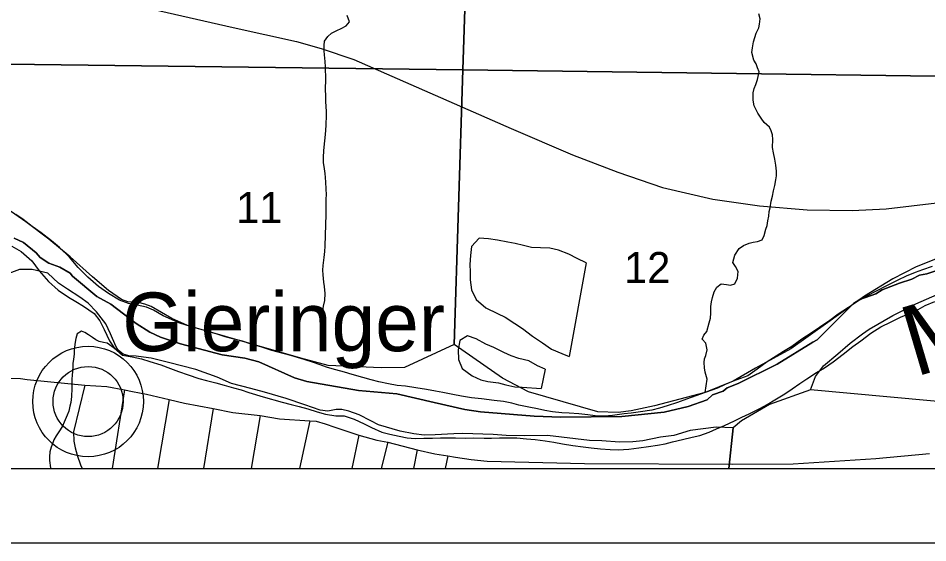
# Model space of a CAD drawing. Extents: x -7.5 to 26.5, y 3.5 to 25.5.
# Drawn here: x -0.973 to 0.251, y 17.5 to 18.207 of the extents above; entities that cross this region are included whole.
import ezdxf

# ---------------------------------------------------------------- set-up
doc = ezdxf.new("R2010")
doc.units = 0
for name, color, linetype in [('GM_X_Corporation', 7, 'Continuous'), ('GM_X_County_Road', 7, 'Continuous'), ('GM_X_Major_River', 7, 'Continuous'), ('GM_X_Major_River_Text', 7, 'Continuous'), ('GM_X_Minor_Lake', 7, 'Continuous'), ('GM_X_Minor_River', 7, 'Continuous'), ('GM_X_Section_Text', 7, 'Continuous'), ('GM_X_State_Route', 7, 'Continuous'), ('GM_X_Township_Road', 7, 'Continuous'), ('GM_X_Unincorporated', 7, 'Continuous'), ('GM_X_Unincorporated_Location', 7, 'Continuous'), ('GM_X_Unincorporated_Text', 7, 'Continuous'), ('SH_Data', 7, 'Continuous')]:
    doc.layers.add(name, color=color, linetype=linetype)

msp = doc.modelspace()

# ---------------------------------------------------------------- linework, layer by layer
at = {"layer": 'GM_X_Corporation'}
for points in [[(-5.2848, 19.2392), (-5.3003, 18.6476), (-5.3247, 17.7117), (-5.3276, 17.6), (1.4431, 17.6), (1.4431, 24.4)], [(-1.2757, 18.1481), (-0.3746, 18.1372), (-0.3863, 17.767), (-0.4529, 17.736), (-0.4844, 17.7357), (-0.5559, 17.7389), (-0.5924, 17.7489), (-0.7267, 17.7874), (-0.7418, 17.7915), (-0.7662, 17.802), (-0.7942, 17.8182), (-0.8024, 17.8214), (-0.8111, 17.8235), (-0.8255, 17.8246), (-0.8341, 17.8279), (-0.8516, 17.84), (-0.8732, 17.8584), (-0.9032, 17.8852), (-0.9318, 17.909), (-0.9627, 17.9325), (-0.988, 17.9498)], [(0.264, 17.8831), (0.2357, 17.8716), (0.2042, 17.8557), (0.1662, 17.8324), (0.1168, 17.7968), (0.0667, 17.7613), (0.0191, 17.7352), (-0.0109, 17.7177), (-0.0484, 17.7027), (-0.1166, 17.6847), (-0.1479, 17.6779), (-0.1654, 17.6756), (-0.193, 17.6763), (-0.2863, 17.7032), (-0.3211, 17.7218), (-0.3863, 17.767), (-0.3746, 18.1372), (0.6301, 18.1235)], [(0.2877, 17.875), (0.2497, 17.8623), (0.2401, 17.8607), (0.2296, 17.855), (0.2131, 17.8499), (0.19, 17.8408), (0.1811, 17.8354), (0.1596, 17.8278), (0.1513, 17.8223), (0.1025, 17.7734), (0.0966, 17.7701), (0.0484, 17.7408), (-0.0041, 17.7145), (-0.0188, 17.7089), (-0.0242, 17.7042), (-0.0385, 17.6994), (-0.0459, 17.6928), (-0.0712, 17.6838), (-0.1034, 17.6758), (-0.1605, 17.6702), (-0.2426, 17.6692), (-0.2786, 17.6704), (-0.3509, 17.6764), (-0.3717, 17.6794), (-0.4131, 17.6888), (-0.4636, 17.7008), (-0.515, 17.7052), (-0.5845, 17.7171), (-0.601, 17.7222), (-0.6492, 17.744), (-0.6681, 17.7489), (-0.6983, 17.7533), (-0.7547, 17.7682), (-0.7814, 17.7771), (-0.7959, 17.7837), (-0.8141, 17.7953), (-0.8485, 17.8216), (-0.8672, 17.8317), (-0.9, 17.8591), (-0.9029, 17.863), (-0.9171, 17.8711), (-0.9317, 17.8765), (-0.9432, 17.8841), (-0.9487, 17.8904), (-0.966, 17.9043), (-0.9784, 17.9104)], [(-0.9784, 17.9104), (-0.966, 17.9043), (-0.9487, 17.8904), (-0.9432, 17.8841), (-0.9317, 17.8765), (-0.9171, 17.8711), (-0.9029, 17.863), (-0.9, 17.8591), (-0.8672, 17.8317), (-0.8485, 17.8216), (-0.8141, 17.7953), (-0.7959, 17.7837), (-0.7814, 17.7771), (-0.7547, 17.7682), (-0.6983, 17.7533), (-0.6681, 17.7489), (-0.6492, 17.744), (-0.601, 17.7222), (-0.5845, 17.7171), (-0.515, 17.7052), (-0.4636, 17.7008), (-0.4131, 17.6888), (-0.3717, 17.6794), (-0.3509, 17.6764), (-0.2786, 17.6704), (-0.2426, 17.6692), (-0.1605, 17.6702), (-0.1034, 17.6758), (-0.0712, 17.6838), (-0.0459, 17.6928), (-0.0385, 17.6994), (-0.0242, 17.7042), (-0.0188, 17.7089), (-0.0041, 17.7145), (0.0484, 17.7408), (0.0966, 17.7701), (0.1025, 17.7734), (0.1513, 17.8223), (0.1596, 17.8278), (0.1811, 17.8354), (0.19, 17.8408), (0.2131, 17.8499), (0.2296, 17.855), (0.2401, 17.8607), (0.2497, 17.8623), (0.2877, 17.875)], [(-1.0391, 17.6), (-0.0167, 17.6), (-0.0109, 17.6548), (-0.0336, 17.6558), (-0.0686, 17.6513), (-0.0907, 17.6447), (-0.1086, 17.6424), (-0.1322, 17.6373), (-0.1459, 17.6361), (-0.1637, 17.6354), (-0.1875, 17.6372), (-0.2042, 17.6379), (-0.2604, 17.6446), (-0.2915, 17.6442), (-0.3161, 17.6444), (-0.3339, 17.646), (-0.3748, 17.6474), (-0.3869, 17.6469), (-0.412, 17.6456), (-0.4267, 17.6452), (-0.4407, 17.6467), (-0.4588, 17.6505), (-0.4882, 17.6588), (-0.4986, 17.6644), (-0.5143, 17.6724), (-0.5279, 17.6772), (-0.5373, 17.6794), (-0.5449, 17.6795), (-0.5563, 17.6775), (-0.5665, 17.6785), (-0.5871, 17.6859), (-0.6123, 17.6944), (-0.6413, 17.7031), (-0.6601, 17.7077), (-0.6857, 17.7148), (-0.7052, 17.7232), (-0.7337, 17.7334), (-0.7706, 17.743), (-0.794, 17.7488), (-0.8042, 17.7502), (-0.814, 17.7512), (-0.8242, 17.7519), (-0.8317, 17.7539), (-0.8384, 17.7594), (-0.8417, 17.7648), (-0.8489, 17.7816), (-0.855, 17.795), (-0.8675, 17.8112), (-0.8789, 17.8229), (-0.8901, 17.8311), (-0.9065, 17.8417), (-0.9188, 17.8496), (-0.9329, 17.8632), (-0.954, 17.8683), (-0.9714, 17.8683), (-0.989, 17.8616)], [(1.0036, 17.6226), (0.0934, 17.7061), (0.0999, 17.7241), (0.1108, 17.7383), (0.1302, 17.7545), (0.1468, 17.7688), (0.1634, 17.7817), (0.1723, 17.7879), (0.2042, 17.8061), (0.2352, 17.822), (0.2708, 17.8378)], [(-2.0482, 17.6), (1.4431, 17.6)]]:
    msp.add_lwpolyline(points, dxfattribs=at)
for points in [[(-0.3419, 19.1283), (-0.3746, 18.1372), (-1.2757, 18.1481), (-1.2769, 18.1576), (-1.2831, 18.1672), (-1.2995, 18.1782), (-1.3164, 18.1862), (-1.3281, 18.1892), (-1.3372, 18.1894), (-1.3579, 18.1948), (-1.3364, 19.1437)], [(0.6477, 19.1133), (0.6301, 18.1235), (-0.3746, 18.1372), (-0.3419, 19.1283)], [(-0.0167, 17.6), (1.0012, 17.6), (1.0036, 17.6226), (0.0934, 17.7061), (0.0383, 17.6862), (0.0007, 17.6644), (-0.0109, 17.6548)]]:
    msp.add_lwpolyline(points, close=True, dxfattribs=at)
at = {"layer": 'GM_X_County_Road'}
for points in [[(-1.131, 17.6), (-1.0978, 17.6932), (-1.0936, 17.7021), (-1.0903, 17.7085), (-1.0871, 17.712), (-1.0841, 17.7149), (-1.0797, 17.7176), (-1.0749, 17.719), (-1.0692, 17.7199), (-1.0658, 17.7203), (-1.0368, 17.7203), (-0.9957, 17.7211), (-0.9844, 17.7216), (-0.9701, 17.7214), (-0.9609, 17.7202), (-0.8832, 17.7124)], [(-0.8832, 17.7124), (-0.8984, 17.6497), (-0.8979, 17.637), (-0.8961, 17.6279), (-0.8935, 17.6182), (-0.8893, 17.6051), (-0.8869, 17.6)], [(-0.8832, 17.7124), (-0.8539, 17.7106), (-0.8297, 17.7061), (-0.8192, 17.704), (-0.8004, 17.7001), (-0.7699, 17.6929), (-0.7493, 17.6881), (-0.7106, 17.6808), (-0.684, 17.6757), (-0.6472, 17.6713), (-0.6215, 17.6671), (-0.5806, 17.6642), (-0.5718, 17.6638), (-0.5597, 17.6603), (-0.547, 17.6559), (-0.5147, 17.6448), (-0.4905, 17.6384), (-0.4755, 17.6355), (-0.4362, 17.6251), (-0.4123, 17.62), (-0.3947, 17.617), (-0.3845, 17.6155), (-0.3633, 17.6122), (-0.3417, 17.6099), (-0.2108, 17.6068), (-0.0112, 17.6061), (0.0701, 17.6063), (0.1811, 17.6136), (0.2534, 17.6204)]]:
    msp.add_lwpolyline(points, dxfattribs=at)
at = {"layer": 'GM_X_Major_River'}
for points in [[(-0.8128, 17.82), (-0.8245, 17.8223), (-0.8366, 17.8269), (-0.8515, 17.8357), (-0.8649, 17.8452), (-0.8793, 17.8578), (-0.8922, 17.8707), (-0.9039, 17.8848), (-0.9175, 17.8977), (-0.9283, 17.9068), (-0.942, 17.9175), (-0.9543, 17.9259), (-0.9665, 17.9354), (-0.9762, 17.9421)], [(-0.9817, 17.8994), (-0.969, 17.8925), (-0.9545, 17.8799), (-0.9447, 17.8663), (-0.9322, 17.8519), (-0.9193, 17.8404), (-0.9052, 17.8309), (-0.8955, 17.8249), (-0.885, 17.8189), (-0.8709, 17.8089), (-0.8629, 17.7988), (-0.8575, 17.7872), (-0.85, 17.7722), (-0.8439, 17.7625), (-0.8324, 17.7527)], [(0.257, 17.8723), (0.2443, 17.8678), (0.234, 17.8639), (0.222, 17.859), (0.2109, 17.8536), (0.1958, 17.8461), (0.1816, 17.839), (0.1696, 17.8325), (0.1595, 17.8267), (0.1444, 17.817), (0.1305, 17.8079), (0.1192, 17.7995), (0.1056, 17.79), (0.0955, 17.7831), (0.0816, 17.7745), (0.068, 17.7646), (0.0571, 17.7577), (0.0471, 17.7512), (0.0351, 17.7436), (0.0215, 17.7338), (0.009, 17.725), (-0.001, 17.7212), (-0.0109, 17.7177), (-0.0213, 17.7134), (-0.0317, 17.7081), (-0.0486, 17.7025), (-0.0736, 17.6934), (-0.0855, 17.6892), (-0.0997, 17.6847), (-0.1097, 17.6816), (-0.12, 17.6785), (-0.1353, 17.6763), (-0.1478, 17.6748), (-0.1574, 17.6736), (-0.173, 17.6714), (-0.1837, 17.6706), (-0.1966, 17.671), (-0.2064, 17.6725), (-0.2185, 17.6736), (-0.2314, 17.6748), (-0.2413, 17.6751), (-0.2537, 17.6766), (-0.2643, 17.6781), (-0.2741, 17.6803), (-0.2858, 17.6829), (-0.299, 17.6856), (-0.3088, 17.6882), (-0.3198, 17.6904), (-0.3326, 17.6919), (-0.3493, 17.694), (-0.3629, 17.6952), (-0.3765, 17.6975), (-0.3882, 17.6997), (-0.4014, 17.7024), (-0.4112, 17.7043), (-0.4233, 17.7065), (-0.4377, 17.7089), (-0.4517, 17.7108), (-0.463, 17.7119), (-0.4747, 17.7142), (-0.4876, 17.7169), (-0.4981, 17.7195), (-0.509, 17.7225), (-0.5237, 17.7267), (-0.5339, 17.7297), (-0.5455, 17.7331), (-0.5565, 17.7361), (-0.5741, 17.7424), (-0.588, 17.747), (-0.6061, 17.7521), (-0.6317, 17.759), (-0.6464, 17.764), (-0.6595, 17.7678), (-0.6712, 17.7716), (-0.6821, 17.7742), (-0.6945, 17.7776), (-0.7051, 17.781), (-0.7224, 17.7861), (-0.7329, 17.7891), (-0.7468, 17.7933), (-0.7566, 17.7963), (-0.7667, 17.8008), (-0.778, 17.8057), (-0.7907, 17.8133), (-0.8004, 17.8174), (-0.8128, 17.82)], [(-0.8324, 17.7527), (-0.8196, 17.7507), (-0.8071, 17.7477), (-0.7958, 17.7443), (-0.7812, 17.7397), (-0.768, 17.7347), (-0.7571, 17.7306), (-0.7444, 17.7264), (-0.7297, 17.7214), (-0.7195, 17.7188), (-0.7071, 17.7157), (-0.6958, 17.7123), (-0.683, 17.7089), (-0.6728, 17.7059), (-0.6627, 17.7026), (-0.6431, 17.6966), (-0.6175, 17.6894), (-0.6058, 17.6864), (-0.5949, 17.6837), (-0.5832, 17.6803), (-0.5708, 17.6765), (-0.5592, 17.6735), (-0.5456, 17.6712), (-0.5342, 17.6712), (-0.521, 17.6666), (-0.5072, 17.6601), (-0.4974, 17.6553), (-0.4836, 17.6492), (-0.4727, 17.6462), (-0.4602, 17.6435), (-0.4493, 17.6416), (-0.4387, 17.6405), (-0.4269, 17.6409), (-0.4155, 17.641), (-0.4045, 17.6414), (-0.395, 17.6415), (-0.3843, 17.6415), (-0.3714, 17.6411), (-0.3604, 17.6412), (-0.346, 17.6411), (-0.3361, 17.6408), (-0.3251, 17.6412), (-0.3129, 17.6416), (-0.3019, 17.6416), (-0.289, 17.6401), (-0.2773, 17.639), (-0.2637, 17.6374), (-0.2523, 17.6355), (-0.2403, 17.6333), (-0.2267, 17.6313), (-0.2127, 17.6294), (-0.2017, 17.6279), (-0.1892, 17.6267), (-0.1763, 17.6256), (-0.1657, 17.6252), (-0.1512, 17.6263), (-0.1379, 17.6278), (-0.1249, 17.6297), (-0.1127, 17.6316), (-0.1024, 17.6335), (-0.0925, 17.6359), (-0.0791, 17.6393), (-0.0657, 17.6423), (-0.0557, 17.6446), (-0.0431, 17.6492), (-0.0331, 17.6534), (-0.0223, 17.658), (-0.0088, 17.6644), (0.0008, 17.6691), (0.0109, 17.6737), (0.0251, 17.6809), (0.0348, 17.6863), (0.0452, 17.6924), (0.0588, 17.7007), (0.0685, 17.7076), (0.079, 17.7145), (0.0886, 17.7207), (0.1014, 17.7294), (0.1123, 17.7359), (0.1239, 17.7439), (0.1372, 17.7541), (0.1504, 17.7643), (0.1609, 17.772), (0.1745, 17.7822), (0.188, 17.7909), (0.2019, 17.7977), (0.2146, 17.8038), (0.2277, 17.8094), (0.2381, 17.8144), (0.2478, 17.8195), (0.2605, 17.8251)]]:
    msp.add_lwpolyline(points, dxfattribs=at)
at = {"layer": 'GM_X_Minor_Lake'}
for p, q in [((-0.2088, 17.877), (-0.2315, 17.7511)), ((-0.2639, 17.7337), (-0.2691, 17.708))]:
    msp.add_line(p, q, dxfattribs=at)
for points in [[(-0.2088, 17.877), (-0.2205, 17.883), (-0.2317, 17.889), (-0.246, 17.8943), (-0.2573, 17.8969), (-0.2699, 17.8972), (-0.282, 17.8979), (-0.2929, 17.9005), (-0.3043, 17.9031), (-0.3141, 17.9049), (-0.3277, 17.9075), (-0.3398, 17.9093), (-0.3527, 17.9104), (-0.3629, 17.8993), (-0.3644, 17.8868), (-0.3651, 17.8747), (-0.3649, 17.8648), (-0.3645, 17.8542), (-0.3629, 17.8408), (-0.3568, 17.8277), (-0.3434, 17.8167), (-0.328, 17.8091), (-0.3175, 17.8039), (-0.3045, 17.7952), (-0.2944, 17.7889), (-0.2806, 17.7782), (-0.2675, 17.7692), (-0.2552, 17.7609), (-0.2413, 17.7548), (-0.2315, 17.7511)], [(-0.2639, 17.7337), (-0.274, 17.7382), (-0.2856, 17.7453), (-0.2992, 17.7483), (-0.3094, 17.7517), (-0.3192, 17.7565), (-0.3327, 17.7629), (-0.3436, 17.7677), (-0.3567, 17.7749), (-0.3683, 17.779), (-0.3784, 17.7725), (-0.381, 17.76), (-0.3802, 17.7471), (-0.3756, 17.7348), (-0.3618, 17.7249), (-0.3505, 17.7197), (-0.3407, 17.7172), (-0.3267, 17.7153), (-0.3169, 17.7127), (-0.3044, 17.7101), (-0.2949, 17.7095), (-0.2691, 17.708)]]:
    msp.add_lwpolyline(points, dxfattribs=at)
at = {"layer": 'GM_X_Minor_River'}
for points in [[(-0.5649, 17.8001), (-0.5629, 17.8121), (-0.5623, 17.8186), (-0.5601, 17.8265), (-0.5598, 17.836), (-0.5606, 17.8451), (-0.5615, 17.8512), (-0.5627, 17.8611), (-0.5629, 17.8672), (-0.5626, 17.8737), (-0.5611, 17.8843), (-0.5605, 17.8922), (-0.5599, 17.8994), (-0.5593, 17.9142), (-0.5584, 17.9423), (-0.5586, 17.9476), (-0.5584, 17.9632), (-0.5582, 17.9689), (-0.5583, 17.9769), (-0.5588, 17.9856), (-0.5593, 17.9921), (-0.5599, 17.9974), (-0.5611, 18.007), (-0.5621, 18.012), (-0.5622, 18.0188), (-0.5615, 18.0283), (-0.5603, 18.0415), (-0.5592, 18.0498), (-0.5584, 18.062), (-0.5579, 18.0764), (-0.5581, 18.0817), (-0.5587, 18.0867), (-0.5588, 18.0954), (-0.559, 18.1004), (-0.5593, 18.1125), (-0.559, 18.1228), (-0.5591, 18.13), (-0.5593, 18.1353), (-0.5595, 18.1411), (-0.56, 18.1483), (-0.5608, 18.1571), (-0.561, 18.1628), (-0.5612, 18.17), (-0.5606, 18.1757), (-0.5562, 18.182), (-0.5511, 18.1867), (-0.5441, 18.1899), (-0.5384, 18.1928), (-0.5318, 18.1963), (-0.5272, 18.2019), (-0.5302, 18.2103)], [(-0.0483, 17.7026), (-0.0459, 17.7206), (-0.0482, 17.7298), (-0.0491, 17.7355), (-0.0497, 17.7427), (-0.0491, 17.7477), (-0.0474, 17.7525), (-0.0456, 17.7601), (-0.0476, 17.7689), (-0.0524, 17.7744), (-0.0503, 17.7796), (-0.0463, 17.7848), (-0.0429, 17.7961), (-0.0411, 17.8028), (-0.0409, 17.8093), (-0.0406, 17.8184), (-0.04, 17.8245), (-0.0387, 17.8305), (-0.0365, 17.838), (-0.0325, 17.8443), (-0.027, 17.8487), (-0.0198, 17.8481), (-0.0142, 17.8471), (-0.0084, 17.8488), (-0.0047, 17.8567), (-0.0041, 17.8654), (-0.0076, 17.872), (-0.0112, 17.8778), (-0.0086, 17.8876), (-0.0026, 17.8965), (0.0032, 17.9005), (0.0106, 17.9036), (0.0163, 17.905), (0.022, 17.9059), (0.0282, 17.908), (0.031, 17.9139), (0.0332, 17.9226), (0.0349, 17.9275), (0.0359, 17.9339), (0.0372, 17.9399), (0.0378, 17.9464), (0.0392, 17.9513), (0.0402, 17.9604), (0.0424, 17.9671), (0.0434, 17.9743), (0.0455, 17.9815), (0.0465, 17.989), (0.0475, 17.9943), (0.0477, 18.0004), (0.0468, 18.0088), (0.0452, 18.0168), (0.0436, 18.0252), (0.0423, 18.0325), (0.0427, 18.0431), (0.0422, 18.0496), (0.0404, 18.055), (0.038, 18.06), (0.031, 18.0663), (0.027, 18.0721), (0.0223, 18.0788), (0.0177, 18.0884), (0.016, 18.0961), (0.016, 18.1063), (0.0174, 18.112), (0.0198, 18.1172), (0.0219, 18.124), (0.0242, 18.1346), (0.0221, 18.1399), (0.02, 18.145), (0.0171, 18.15), (0.0145, 18.1603), (0.0151, 18.1668), (0.0165, 18.1747), (0.0186, 18.1807), (0.0203, 18.1867), (0.0236, 18.1935), (0.0249, 18.1984), (0.0255, 18.2059), (0.0239, 18.2125)], [(-0.8421, 17.761), (-0.8533, 17.769), (-0.8582, 17.7699), (-0.8638, 17.7713), (-0.8683, 17.7733), (-0.8731, 17.7765), (-0.8783, 17.7801), (-0.8835, 17.7833), (-0.888, 17.785), (-0.8935, 17.7814), (-0.8952, 17.7754), (-0.8965, 17.7701), (-0.8976, 17.7599), (-0.8978, 17.7546), (-0.8984, 17.747), (-0.8994, 17.7421), (-0.8995, 17.7372), (-0.9001, 17.7311), (-0.9003, 17.7254), (-0.9009, 17.7209), (-0.901, 17.7156), (-0.9009, 17.708), (-0.9013, 17.6973), (-0.902, 17.689), (-0.9033, 17.6841), (-0.905, 17.6773), (-0.9071, 17.6721), (-0.9112, 17.6623), (-0.9133, 17.6571), (-0.9185, 17.6497), (-0.9221, 17.6441), (-0.9249, 17.6385), (-0.927, 17.6333), (-0.9287, 17.6288), (-0.9304, 17.6224), (-0.931, 17.6159), (-0.9308, 17.611), (-0.9293, 17.6011), (-0.929, 17.6)]]:
    msp.add_lwpolyline(points, dxfattribs=at)
at = {"layer": 'GM_X_State_Route'}
msp.add_lwpolyline([(-0.9459, 18.2541), (-0.6835, 18.1943), (-0.5985, 18.1752), (-0.5651, 18.1658), (-0.5214, 18.1509), (-0.3094, 18.0583), (-0.227, 18.0224), (-0.1659, 17.9992), (-0.1057, 17.9788), (-0.038, 17.9629), (0.0246, 17.9539), (0.0888, 17.9486), (0.1496, 17.9478), (0.1954, 17.9497), (0.2633, 17.9581)], dxfattribs=at)
at = {"layer": 'GM_X_Township_Road'}
for p, q in [((-0.8297, 17.7061), (-0.8463, 17.6)), ((-0.7699, 17.6929), (-0.7857, 17.6)), ((-0.7106, 17.6808), (-0.7238, 17.6)), ((-0.6472, 17.6713), (-0.6593, 17.6)), ((-0.5806, 17.6642), (-0.5943, 17.6)), ((-0.5147, 17.6448), (-0.524, 17.6)), ((-0.4755, 17.6355), (-0.4846, 17.6)), ((-0.4362, 17.6251), (-0.441, 17.6)), ((-0.3947, 17.617), (-0.3983, 17.6))]:
    msp.add_line(p, q, dxfattribs=at)
at = {"layer": 'GM_X_Unincorporated'}
for radius in [0.0744, 0.0472]:
    msp.add_circle((-0.8789, 17.6903), radius, dxfattribs=at)
at = {"layer": 'GM_X_Unincorporated_Location'}
msp.add_line((-0.8789, 17.6903), (-0.8789, 17.6903), dxfattribs=at)
at = {"layer": 'SH_Data'}
for p, q in [((-5.3569, 17.6), (1.4431, 17.6)), ((-5.4569, 17.5), (1.5431, 17.5))]:
    msp.add_line(p, q, dxfattribs=at)

# ---------------------------------------------------------------- texts
at = {"layer": 'GM_X_Major_River_Text'}
msp.add_text('Miami', height=0.09469, rotation=16.4863, dxfattribs=at).set_placement((0.2341, 17.7233))
at = {"layer": 'GM_X_Section_Text'}
for s, p in [('11', (-0.6797, 17.9307)), ('12', (-0.1576, 17.8498))]:
    msp.add_text(s, height=0.04186, rotation=0, dxfattribs=at).set_placement(p)
at = {"layer": 'GM_X_Unincorporated_Text'}
msp.add_text('Gieringer', height=0.07898, rotation=0, dxfattribs=at).set_placement((-0.833, 17.7581))

doc.saveas('drawing.dxf')
